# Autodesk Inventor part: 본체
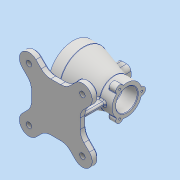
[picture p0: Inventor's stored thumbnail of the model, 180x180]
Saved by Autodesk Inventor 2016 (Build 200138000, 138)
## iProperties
Created: 2018-03
Part Number: 본체
Material: 알루미늄 6061
Document SubType Name: Modeling
Designer: 605-03
Density: 2.7 g/cm^3
Appearance: 알루미늄 - 평지
Mass: 1010.94 g
Surface Area: 854.573 cm^2
Volume: 374.421 cm^3
Author: 605-03
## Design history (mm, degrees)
sketch "스케치2"
  geometry: L1 (45, 45)-(-45, 45); L2 (-45, 45)-(-45, -45); L3 (-45, -45)-(45, -45); L4 (45, -45)-(45, 45); L5 (45, 45)-(-45, -45); L6 (-45, 45)-(45, -45); 1 further point
  constraints: 12 end point, 2 midpoint, 2 parallel, 1 horizontal, 1 perpendicular
  dimensions: "d23" = 90 distance of L2.end L3.end; "d24" = 90 distance of L1.end L2.end
extrude "돌출1" new body sketch "스케치2" distance "d25" = 12; taper "d26" = 0 deg
sketch "스케치3"
  geometry: L1 (0, 0)-(-70, 0); L2 (0, 0)-(-49.497, -49.497); L3 (-62.225, -36.77)-(-9.779, 15.677); L4 (-36.77, -62.225)-(12.81, -12.646); L5 (12.81, -12.646)-(-9.779, 15.677); A1 r 70 centre (0, 0) between (-70, 0) and (-49.497, -49.497); A2 r 18 centre (-49.497, -49.497) between (-62.225, -36.77) and (-36.77, -62.225); 1 further point
  constraints: 10 end point, 4 point on circle, 2 centre point, 2 coincident, 2 tangent, 1 horizontal, 1 parallel
  dimensions: "d27" = 140 diameter of A1; "d28" = 45 deg angle of L1 L2; "d29" = 36 diameter of A2; "d30" = 45 deg angle of L1 L3; "d32" = 96.4261 deg angle of L5 L4; "d33" = 2.12992 distance from line of point (0, 0) L5
extrude "돌출2" join sketch "스케치3" distance "d34" = 12; taper "d35" = 0 deg
sketch "스케치4"
  geometry: C1 r 5 at (49.497, 49.497); A1 r 18 centre (49.497, 49.497) between (62.225, 36.77) and (36.77, 62.225) reference; 1 further point
  constraints: 1 centre point, 1 concentric
  dimensions: "d40" = 10 diameter of C1
extrude "돌출3" cut sketch "스케치4" distance "d41" = 12; taper "d42" = 0 deg
sketch "스케치5"
  geometry: L1 (37, 4)-(-37, 4); L2 (-37, 4)-(-37, -4); L3 (-37, -4)-(37, -4); L4 (37, -4)-(37, 4); L5 (37, 4)-(-37, -4); L6 (-37, 4)-(37, -4); L7 (-19.544, -45)-(19.544, -45) reference; L8 (45, -19.544)-(45, 19.544) reference; 5 further points
  constraints: 12 end point, 6 midpoint, 2 parallel, 1 horizontal, 1 horizontal alignment, 1 perpendicular, 1 vertical alignment
  dimensions: "d95" = 8 distance of L3.end L1.start; "d96" = 74 distance of L2.end L3.end
extrude "돌출4" join sketch "스케치5" distance "d54" = 70; taper "d55" = 0 deg
sketch "스케치6"
  geometry: L1 (-50, 82)-(50, 82); L2 (50, 82)-(50, 109.5); L3 (-30, 127)-(-50, 127); L4 (-50, 127)-(-50, 82); L5 (36.77, 0)-(19.544, 0) reference; L6 (-30, 127)-(27, 109.5); L7 (27, 109.5)-(50, 109.5); 1 further point
  constraints: 12 end point, 2 horizontal, 2 perpendicular, 1 parallel
  dimensions: "d56" = 82 distance between parallel lines of L5 L1; "d57" = 45 distance between parallel lines of L1 L3; "d58" = 20 distance of L3.start L3.end; "d59" = 100 distance between parallel lines of L2 L4; "d60" = 50 distance from line of point (0, 0) L4; "d61" = 27.5 distance of L1.end L2.end; "d65" = 77 horizontal distance of L6.end L3.end
revolve "회전1" sketch "스케치6" stored, may be unused: angle "d62" = 90 deg
node "작업 평면1"
sketch "스케치7"
  geometry: L1 (-27.5, 12.5)-(-52.5, 12.5); L2 (-52.5, 12.5)-(-52.5, -12.5); L3 (-52.5, -12.5)-(-27.5, -12.5); L4 (-27.5, -12.5)-(-27.5, 12.5); L5 (-27.5, 12.5)-(-52.5, -12.5); L6 (-52.5, 12.5)-(-27.5, -12.5); 1 further point
  constraints: 12 end point, 2 midpoint, 2 parallel, 1 horizontal, 1 perpendicular
  dimensions: "d63" = 25 distance of L2.end L3.end; "d64" = 25 distance of L1.end L2.end
extrude "돌출5" join sketch "스케치7" distance "d66" = 20; taper "d67" = 0 deg
fillet "모깎기2" dims "d68" = 8
sketch "스케치8"
  geometry: C1 r 7 at (0, 27.5); 2 further points
  constraints: 2 vertical alignment, 1 centre point, 1 other
  dimensions: "d69" = 14 diameter of C1
extrude "돌출6" join sketch "스케치8" distance "d70" = 15; taper "d71" = 0 deg
node "작업축1"
sketch "스케치9"
  geometry: L1 (-50, 82)-(50, 82); L2 (-50, 82)-(-50, 117); L3 (-50, 117)-(-27, 117); L4 (-27, 117)-(-27, 108); L5 (-27, 108)-(20, 108); L6 (20, 108)-(20, 102); L7 (20, 102)-(50, 102); L8 (50, 102)-(50, 82); L9 (-50, 37)-(-50, 127) reference; 1 further point
  constraints: 16 end point, 3 vertical, 2 horizontal, 2 perpendicular, 1 parallel, 1 point on line
  dimensions: "d75" = 82 distance from line of point (0, 0) L1; "d76" = 35 distance between parallel lines of L1 L3; "d77" = 23 distance of L2.end L3.end; "d78" = 47 distance of L4.end L5.end; "d79" = 26 distance between parallel lines of L1 L5; "d80" = 30 distance of L6.end L7.end; "d81" = 20 distance between parallel lines of L1 L7
revolve "회전2" sketch "스케치9" stored, may be unused: angle "d82" = 90 deg
sketch "스케치10"
  geometry: L1 (47.5, -7.5)-(32.5, -7.5); L2 (32.5, -7.5)-(32.5, 7.5); L3 (32.5, 7.5)-(47.5, 7.5); L4 (47.5, 7.5)-(47.5, -7.5); L5 (47.5, -7.5)-(32.5, 7.5); L6 (32.5, -7.5)-(47.5, 7.5); 1 further point
  constraints: 12 end point, 2 midpoint, 2 parallel, 1 horizontal, 1 perpendicular
  dimensions: "d83" = 15 distance of L2.end L3.end; "d84" = 15 distance of L1.end L2.end
extrude "돌출7" cut sketch "스케치10" distance "d85" = 30; taper "d86" = 0 deg
fillet "모깎기3" dims "d87" = 3
fillet "모깎기4" dims "d88" = 1
chamfer "모따기1" distance "d89" = 1; stored, may be unused: second distance "d90" = 2, angle "d91" = 45 deg
chamfer "모따기2" distance "d92" = 1; stored, may be unused: second distance "d93" = 2, angle "d94" = 45 deg
sketch "스케치11"
  geometry: L1 (12, -20.787)-(12, 20.787) reference; L2 (12, 20.787)-(12, 38.891) reference; L3 (12, 64.497)-(12, 38.891) reference; L4 (12, 24)-(64.68, 19.391); L5 (12, 45)-(12, 4) reference; L6 (12, 4)-(46.435, 4) reference; L7 (116.273, 12.5)-(127, 12.5) reference; L8 (127, 12.5)-(127, 8.5) reference; L9 (127, 8.5)-(126, 7.5) reference; L10 (126, 7.5)-(106.895, 7.5) reference; L11 (106.895, -7.5)-(126, -7.5) reference; L12 (126, -7.5)-(127, -8.5) reference; L13 (127, -8.5)-(127, -12.5) reference; L14 (127, -12.5)-(116.273, -12.5) reference; L15 (46.435, -4)-(12, -4) reference; L16 (12, -4)-(12, -45) reference; L17 (12, -45)-(0, -45) reference; L18 (0, -45)-(0, 45) reference; L19 (0, 45)-(12, 45) reference; L20 (12, 24)-(12, 0); L21 (12, 0)-(56, 0); A1 r 35.789 centre (82, 0) between (115.287, 13.149) and (46.435, 4) reference; A2 r 26 centre (82, 0) between (106.895, 7.5) and (106.895, -7.5) reference; A3 r 35.789 centre (82, 0) between (46.435, -4) and (115.287, -13.149) reference; 2 further points
  constraints: 6 end point, 2 point on circle, 1 midpoint, 1 point on line, 2 other
  dimensions: "d97" = 24 vertical distance of point (0, 0) L4.start; "d98" = 95 deg angle of L2 L4
extrude "돌출8" join sketch "스케치11" stored distance "d99" = 8; taper "d100" = 0 deg
sketch "스케치12"
  geometry: C1 r 36 at (0, 0) reference; 2 further points
  constraints: 1 vertical alignment
  dimensions: "d101" = 40 distance of C1.centre point (0, 40)
hole "구멍1" sketch "스케치12" at (0, 40) diameter "d102" = 3.459; stored, may be unused: countersink angle "d106" = 90 deg, drill point angle "d108" = 118 deg; dims "d103" = 9, "d104" = 4, "d105" = 2, "d107" = 11
sketch "스케치13"
  geometry: C1 r 20 at (0, -27.5) reference; 2 further points
  constraints: 1 vertical alignment
  dimensions: "d112" = 27.5 distance of C1.centre point (0, 0)
hole "구멍2" sketch "스케치13" at (0, 0) diameter "d113" = 3.459; stored, may be unused: countersink angle "d117" = 90 deg, drill point angle "d119" = 118 deg; dims "d114" = 9, "d115" = 4, "d116" = 2, "d118" = 11
fillet "모깎기5" dims "d123" = 3
fillet "모깎기6" dims "d124" = 3
fillet "모깎기7" dims "d125" = 3
fillet "모깎기8" dims "d126" = 3
fillet "모깎기9" dims "d127" = 3
fillet "모깎기10" dims "d128" = 1
fillet "모깎기11" dims "d132" = 3
chamfer "모따기3" distance "d133" = 1; stored, may be unused: second distance "d134" = 2, angle "d135" = 45 deg
sketch "스케치14"
  geometry: L1 (45, -19.544)-(45, 19.544) reference; 2 further points
  constraints: 1 other
  dimensions: "d136" = 45 distance from line of point (0, -35) L1; "d137" = 35 distance of point (0, 0) point (0, -35)
extrude "돌출9" join sketch "스케치14" distance "d138" = 0.5; taper "d139" = 0 deg
fillet "모깎기12" dims "d140" = 3
node "작업축2"
fillet "모깎기13" dims "d141" = 25
chamfer "모따기4" distance "d142" = 3; stored, may be unused: second distance "d143" = 2, angle "d144" = 45 deg
node "솔리드1"
pattern_circular "원형 패턴1" dims angle "d37" = 360 deg
pattern_circular "원형 패턴2" dims angle "d44" = 360 deg
pattern_circular "원형 패턴3" dims angle "d73" = 360 deg
mirror "대칭1"
pattern_circular "원형 패턴4" dims angle "d110" = 360 deg
pattern_circular "원형 패턴5" dims angle "d121" = 360 deg
pattern_circular "원형 패턴6" dims angle "d130" = 360 deg
node "투영된 루프1"
node "절단 모서리 투영1"
